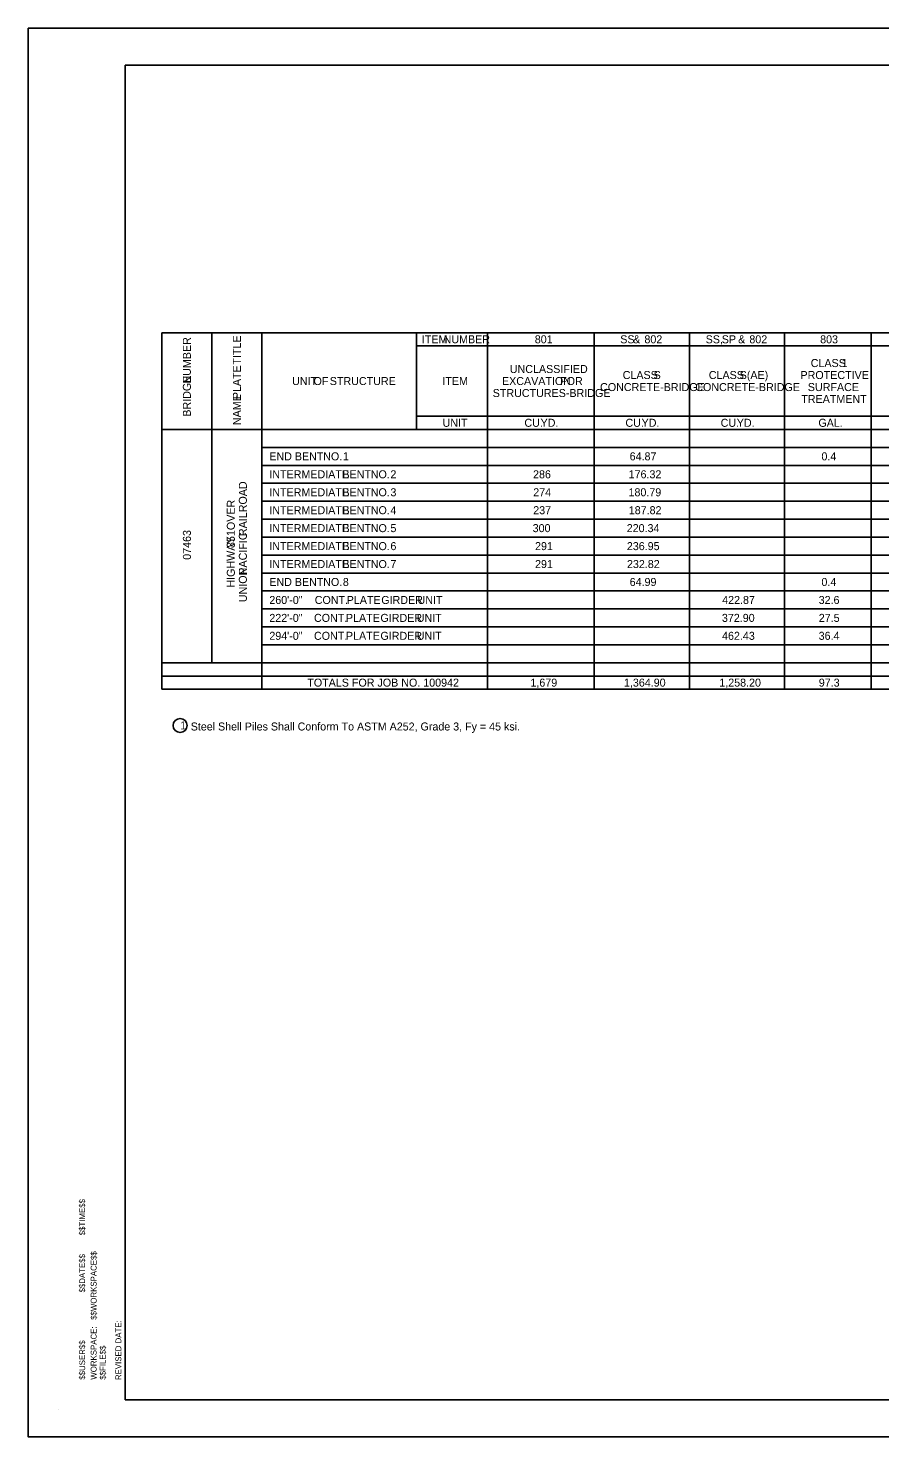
# Model space of a CAD drawing. Extents: x -129 to 14744569, y -102 to 1829048.
# Drawn here: x -129.13 to -115.83, y -101.98 to -79.98 of the extents above; entities that cross this region are included whole.
import ezdxf

# ---------------------------------------------------------------- set-up
doc = ezdxf.new("R2010")
doc.units = 0
for name, color, linetype in [('B_Dimensions', 7, 'Continuous'), ('B_Text', 7, 'Continuous'), ('B_Title Text', 7, 'Continuous'), ('R_Border', 7, 'Continuous')]:
    doc.layers.add(name, color=color, linetype=linetype)

msp = doc.modelspace()

# ---------------------------------------------------------------- linework, layer by layer
at = {"layer": 'B_Text'}
msp.add_line((-127.044, -84.735), (-127.044, -84.735), dxfattribs=at)
msp.add_circle((-126.76, -90.87), 0.11, dxfattribs=at)
at = {"layer": 'B_Title Text'}
for p, q in [((-127.044, -84.735), (-96.527, -84.735)), ((-127.044, -90.304), (-127.044, -84.735)), ((-126.265, -89.89), (-126.265, -84.735)), ((-125.485, -90.304), (-125.485, -84.735)), ((-123.071, -86.246), (-123.071, -84.735)), ((-121.962, -90.304), (-121.962, -84.735)), ((-120.293, -90.304), (-120.293, -84.735)), ((-118.806, -90.304), (-118.806, -84.735)), ((-117.319, -90.304), (-117.319, -84.735)), ((-115.966, -90.304), (-115.966, -84.735)), ((-123.071, -84.942), (-96.527, -84.942)), ((-123.071, -86.039), (-96.527, -86.039)), ((-127.044, -86.246), (-96.527, -86.246)), ((-125.485, -86.526), (-96.527, -86.526)), ((-125.485, -86.807), (-96.527, -86.807)), ((-125.485, -87.087), (-96.527, -87.087)), ((-125.485, -87.367), (-96.527, -87.367)), ((-125.485, -87.648), (-96.527, -87.648)), ((-125.485, -87.928), (-96.527, -87.928)), ((-125.485, -88.208), (-96.527, -88.208)), ((-125.485, -88.489), (-96.527, -88.489)), ((-125.485, -88.769), (-96.527, -88.769)), ((-125.485, -89.049), (-96.527, -89.049)), ((-125.485, -89.329), (-96.527, -89.329)), ((-125.485, -89.61), (-96.527, -89.61)), ((-127.044, -89.89), (-96.527, -89.89)), ((-127.044, -90.097), (-96.527, -90.097)), ((-127.044, -90.304), (-96.527, -90.304))]:
    msp.add_line(p, q, dxfattribs=at)
at = {"layer": 'R_Border'}
for p, q in [((-127.618, -80.556), (-95.711, -80.556)), ((-127.618, -101.403), (-127.618, -80.556)), ((-95.711, -101.403), (-127.618, -101.403)), ((-128.666, -101.552), (-128.666, -101.552))]:
    msp.add_line(p, q, dxfattribs=at)
msp.add_lwpolyline([(-129.134, -79.979), (-95.134, -79.979), (-95.134, -101.979), (-129.134, -101.979)], close=True, dxfattribs=at)

# ---------------------------------------------------------------- texts
at = {"layer": 'B_Dimensions'}
msp.add_text('1', height=0.125, rotation=360, dxfattribs=at).set_placement((-126.76, -90.932))
at = {"layer": 'B_Text'}
for s, p in [(' NUMBER', (-126.592, -85.576)), (' TITLE', (-125.812, -85.28)), (' PLATE', (-125.812, -85.82)), ('BRIDGE', (-126.592, -86.047)), ('NAME', (-125.812, -86.179)), (' RAILROAD', (-125.718, -87.958)), (' OVER', (-125.906, -87.865)), ('07463', (-126.592, -88.282)), (' 351', (-125.906, -88.144)), ('HIGHWAY', (-125.906, -88.717)), (' PACIFIC', (-125.718, -88.561)), ('UNION', (-125.718, -88.944))]:
    msp.add_text(s, height=0.125, rotation=90, dxfattribs=at).set_placement(p)
for s, height, p in [('ITEM', 0.125, (-122.985, -84.901)), (' NUMBER', 0.125, (-122.691, -84.901)), ('801', 0.125, (-121.221, -84.901)), ('SS', 0.125, (-119.886, -84.901)), (' &', 0.125, (-119.731, -84.901)), (' 802', 0.125, (-119.555, -84.901)), ('SS,', 0.125, (-118.552, -84.901)), (' SP', 0.125, (-118.347, -84.901)), (' &', 0.125, (-118.091, -84.901)), (' 802', 0.125, (-117.916, -84.901)), ('803', 0.125, (-116.764, -84.901)), ('UNCLASSIFIED', 0.125, (-121.611, -85.365)), ('CLASS', 0.125, (-119.848, -85.459)), (' S', 0.125, (-119.411, -85.459)), ('CLASS', 0.125, (-118.503, -85.459)), (' S(AE)', 0.125, (-118.067, -85.459)), ('PROTECTIVE', 0.125, (-117.071, -85.459)), ('CLASS', 0.125, (-116.911, -85.272)), (' 1', 0.125, (-116.474, -85.272)), ('UNIT', 0.125, (-125.012, -85.553)), (' OF', 0.125, (-124.723, -85.553)), (' STRUCTURE', 0.125, (-124.469, -85.553)), ('ITEM', 0.125, (-122.664, -85.553)), ('EXCAVATION', 0.125, (-121.733, -85.553)), (' FOR', 0.125, (-120.871, -85.553)), ('CONCRETE-BRIDGE', 0.125, (-120.201, -85.647)), ('CONCRETE-BRIDGE', 0.125, (-118.714, -85.647)), ('SURFACE', 0.125, (-116.956, -85.647)), ('STRUCTURES-BRIDGE', 0.125, (-121.878, -85.74)), ('TREATMENT', 0.125, (-117.058, -85.834)), ('UNIT', 0.125, (-122.661, -86.205)), ('CU.', 0.125, (-121.383, -86.205)), (' YD.', 0.125, (-121.177, -86.205)), ('CU.', 0.125, (-119.805, -86.205)), (' YD.', 0.125, (-119.599, -86.205)), ('CU.', 0.125, (-118.318, -86.205)), (' YD.', 0.125, (-118.112, -86.205)), ('GAL.', 0.125, (-116.791, -86.205)), ('  END', 0.125, (-125.46, -86.729)), (' BENT', 0.125, (-125.015, -86.729)), (' NO.', 0.125, (-124.572, -86.729)), (' 1', 0.125, (-124.265, -86.729)), ('64.87', 0.125, (-119.739, -86.729)), ('0.4', 0.125, (-116.744, -86.729)), ('  INTERMEDIATE', 0.125, (-125.46, -87.009)), (' BENT', 0.125, (-124.272, -87.009)), (' NO.', 0.125, (-123.829, -87.009)), (' 2', 0.125, (-123.522, -87.009)), ('286', 0.125, (-121.248, -87.009)), ('176.32', 0.125, (-119.755, -87.009)), ('  INTERMEDIATE', 0.125, (-125.46, -87.29)), (' BENT', 0.125, (-124.272, -87.29)), (' NO.', 0.125, (-123.829, -87.29)), (' 3', 0.125, (-123.522, -87.29)), ('274', 0.125, (-121.245, -87.29)), ('180.79', 0.125, (-119.757, -87.29)), ('  INTERMEDIATE', 0.125, (-125.46, -87.57)), (' BENT', 0.125, (-124.272, -87.57)), (' NO.', 0.125, (-123.829, -87.57)), (' 4', 0.125, (-123.522, -87.57)), ('237', 0.125, (-121.245, -87.57)), ('187.82', 0.125, (-119.753, -87.57)), ('  INTERMEDIATE', 0.125, (-125.46, -87.85)), (' BENT', 0.125, (-124.272, -87.85)), (' NO.', 0.125, (-123.829, -87.85)), (' 5', 0.125, (-123.522, -87.85)), ('300', 0.125, (-121.254, -87.85)), ('220.34', 0.125, (-119.785, -87.85)), ('  INTERMEDIATE', 0.125, (-125.46, -88.131)), (' BENT', 0.125, (-124.272, -88.131)), (' NO.', 0.125, (-123.829, -88.131)), (' 6', 0.125, (-123.522, -88.131)), ('291', 0.125, (-121.217, -88.131)), ('236.95', 0.125, (-119.783, -88.131)), ('  INTERMEDIATE', 0.125, (-125.46, -88.411)), (' BENT', 0.125, (-124.272, -88.411)), (' NO.', 0.125, (-123.829, -88.411)), (' 7', 0.125, (-123.522, -88.411)), ('291', 0.125, (-121.217, -88.411)), ('232.82', 0.125, (-119.781, -88.411)), ('  END', 0.125, (-125.46, -88.691)), (' BENT', 0.125, (-125.015, -88.691)), (' NO.', 0.125, (-124.572, -88.691)), (' 8', 0.125, (-124.265, -88.691)), ('64.99', 0.125, (-119.739, -88.691)), ('0.4', 0.125, (-116.744, -88.691)), ('  260\'-0"', 0.125, (-125.46, -88.972)), (' CONT.', 0.125, (-124.704, -88.972)), (' PLATE', 0.125, (-124.205, -88.972)), (' GIRDER', 0.125, (-123.665, -88.972)), (' UNIT', 0.125, (-123.098, -88.972)), ('422.87', 0.125, (-118.294, -88.972)), ('32.6', 0.125, (-116.787, -88.972)), ('  222\'-0"', 0.125, (-125.46, -89.252)), (' CONT.', 0.125, (-124.716, -89.252)), (' PLATE', 0.125, (-124.217, -89.252)), (' GIRDER', 0.125, (-123.678, -89.252)), (' UNIT', 0.125, (-123.111, -89.252)), ('372.90', 0.125, (-118.298, -89.252)), ('27.5', 0.125, (-116.785, -89.252)), ('  294\'-0"', 0.125, (-125.46, -89.532)), (' CONT.', 0.125, (-124.716, -89.532)), (' PLATE', 0.125, (-124.217, -89.532)), (' GIRDER', 0.125, (-123.678, -89.532)), (' UNIT', 0.125, (-123.111, -89.532)), ('462.43', 0.125, (-118.296, -89.532)), ('36.4', 0.125, (-116.787, -89.532)), ('TOTALS FOR JOB NO. 100942', 0.125, (-124.774, -90.263)), ('1,679', 0.125, (-121.289, -90.263)), ('1,364.90', 0.125, (-119.828, -90.263)), ('1,258.20', 0.125, (-118.339, -90.263)), ('97.3', 0.125, (-116.785, -90.263)), ('Steel Shell Piles Shall Conform To ASTM A252, Grade 3, Fy = 45 ksi.', 0.1248, (-126.595, -90.948))]:
    msp.add_text(s, height=height, dxfattribs=at).set_placement(p)
at = {"layer": 'R_Border'}
for s, p in [('$$TIME$$', (-128.244, -98.832)), ('$$DATE$$', (-128.244, -99.725)), ('$$WORKSPACE$$', (-128.065, -100.152)), ('WORKSPACE:', (-128.065, -101.087)), ('REVISED DATE:', (-127.679, -101.093)), ('$$USER$$', (-128.244, -101.087)), ('$$FILE$$', (-127.923, -101.087))]:
    msp.add_text(s, height=0.0918, rotation=90, dxfattribs=at).set_placement(p)

doc.saveas('drawing.dxf')
